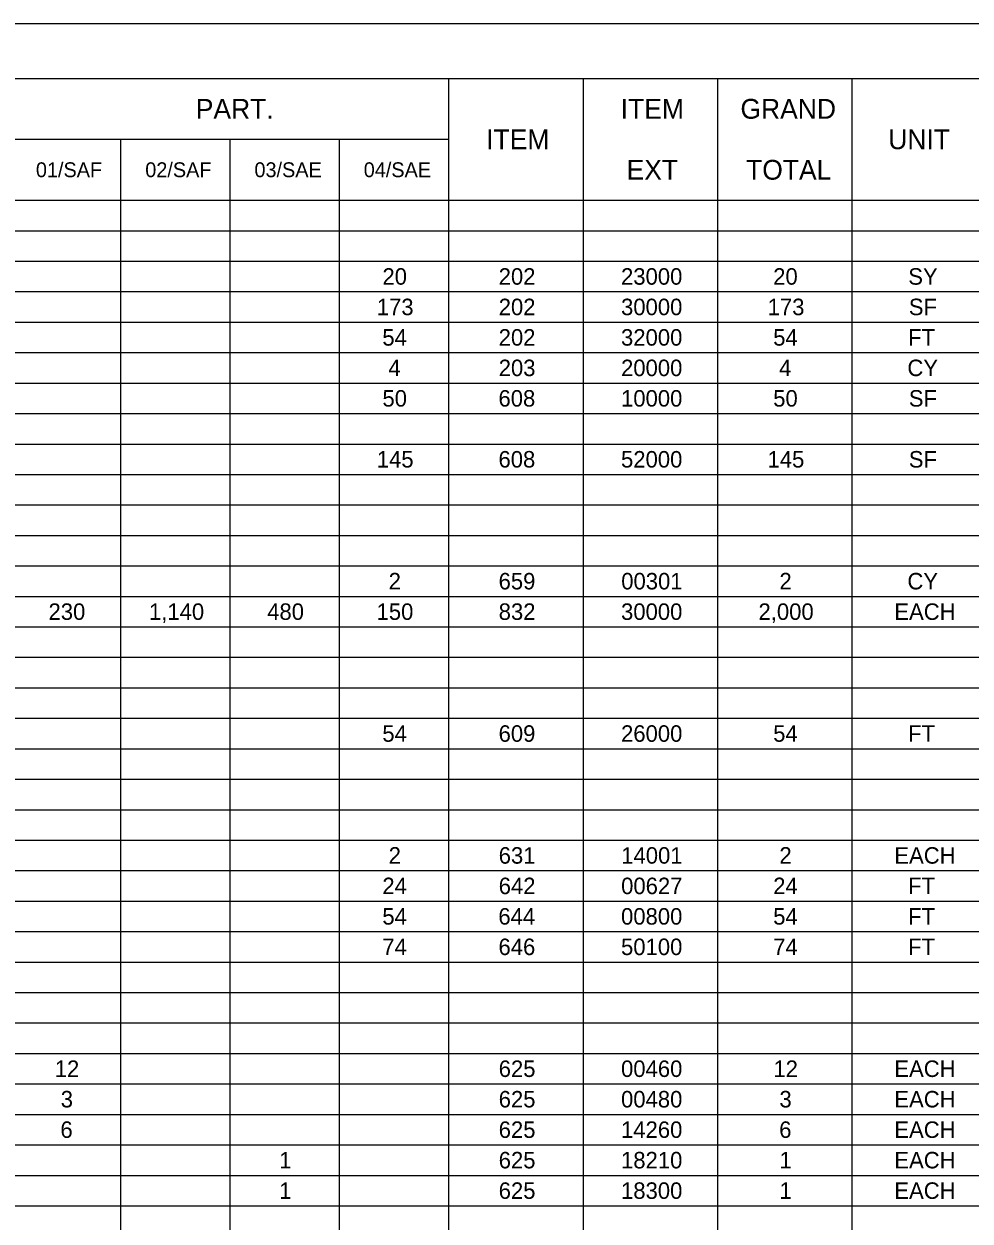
# Model space of a CAD drawing. Extents: x 0 to 34, y 0 to 22.
# Drawn here: x 8.65 to 17.34, y 11 to 22 of the extents above; entities that cross this region are included whole.
import ezdxf

# ---------------------------------------------------------------- set-up
doc = ezdxf.new("R2010")
doc.units = 0
for name, color, linetype in [('Default', 7, 'Continuous'), ('SH_Border', 7, 'Continuous'), ('SH_Cut_Line', 7, 'Continuous')]:
    doc.layers.add(name, color=color, linetype=linetype)

msp = doc.modelspace()

# ---------------------------------------------------------------- linework, layer by layer
at = {"layer": 'Default'}
for p, q in [((1.5, 21.5), (32, 21.5)), ((12.55, 21.5), (12.55, 0.5)), ((13.786, 21.5), (13.786, 0.5)), ((15.021, 21.5), (15.021, 0.5)), ((16.256, 21.5), (16.256, 0.5)), ((1.5, 20.94), (12.55, 20.94)), ((9.537, 20.94), (9.537, 0.5)), ((10.541, 20.94), (10.541, 0.5)), ((11.546, 20.94), (11.546, 0.5)), ((1.5, 20.38), (32, 20.38)), ((1.5, 20.1), (32, 20.1)), ((1.5, 19.82), (32, 19.82)), ((1.5, 19.54), (32, 19.54)), ((1.5, 19.26), (32, 19.26)), ((1.5, 18.98), (32, 18.98)), ((1.5, 18.7), (32, 18.7)), ((1.5, 18.42), (32, 18.42)), ((1.5, 18.14), (32, 18.14)), ((1.5, 17.86), (32, 17.86)), ((1.5, 17.58), (32, 17.58)), ((1.5, 17.3), (32, 17.3)), ((1.5, 17.02), (32, 17.02)), ((1.5, 16.74), (32, 16.74)), ((1.5, 16.46), (32, 16.46)), ((1.5, 16.18), (32, 16.18)), ((1.5, 15.9), (32, 15.9)), ((1.5, 15.62), (32, 15.62)), ((1.5, 15.34), (32, 15.34)), ((1.5, 15.06), (32, 15.06)), ((1.5, 14.78), (32, 14.78)), ((1.5, 14.5), (32, 14.5)), ((1.5, 14.22), (32, 14.22)), ((1.5, 13.94), (32, 13.94)), ((1.5, 13.66), (32, 13.66)), ((1.5, 13.38), (32, 13.38)), ((1.5, 13.1), (32, 13.1)), ((1.5, 12.82), (32, 12.82)), ((1.5, 12.54), (32, 12.54)), ((1.5, 12.26), (32, 12.26)), ((1.5, 11.98), (32, 11.98)), ((1.5, 11.7), (32, 11.7)), ((1.5, 11.42), (32, 11.42)), ((1.5, 11.14), (32, 11.14))]:
    msp.add_line(p, q, dxfattribs=at)
at = {"layer": 'SH_Border'}
msp.add_lwpolyline([(1.5, 21.5), (33.5, 21.5), (33.5, 0.5), (1.5, 0.5)], close=True, dxfattribs=at)
at = {"layer": 'SH_Cut_Line'}
msp.add_lwpolyline([(0, 0), (34, 0), (34, 22), (0, 22)], close=True, dxfattribs=at)

# ---------------------------------------------------------------- texts
at = {"layer": 'Default'}
for s, height, p in [('PART.', 0.1818, (10.228, 21.129)), ('ITEM', 0.1818, (14.132, 21.129)), ('GRAND', 0.1818, (15.232, 21.129)), ('ITEM', 0.1818, (12.896, 20.849)), ('UNIT', 0.1818, (16.59, 20.849)), ('01/SAF', 0.1364, (8.759, 20.592)), ('02/SAF', 0.1364, (9.764, 20.592)), ('03/SAE', 0.1364, (10.767, 20.592)), ('04/SAE', 0.1364, (11.771, 20.592)), ('EXT', 0.1818, (14.186, 20.569)), ('TOTAL', 0.1818, (15.284, 20.569)), ('20', 0.1515, (11.943, 19.604)), ('202', 0.1515, (13.011, 19.604)), ('23000', 0.1515, (14.135, 19.604)), ('20', 0.1515, (15.533, 19.604)), ('SY', 0.1515, (16.774, 19.604)), ('173', 0.1515, (11.891, 19.324)), ('202', 0.1515, (13.011, 19.324)), ('30000', 0.1515, (14.135, 19.324)), ('173', 0.1515, (15.482, 19.324)), ('SF', 0.1515, (16.779, 19.324)), ('54', 0.1515, (11.942, 19.044)), ('202', 0.1515, (13.011, 19.044)), ('32000', 0.1515, (14.135, 19.044)), ('54', 0.1515, (15.533, 19.044)), ('FT', 0.1515, (16.773, 19.044)), ('4', 0.152, (11.997, 18.764)), ('203', 0.1515, (13.011, 18.764)), ('20000', 0.1515, (14.135, 18.764)), ('4', 0.152, (15.587, 18.764)), ('CY', 0.1515, (16.766, 18.764)), ('50', 0.1515, (11.943, 18.484)), ('608', 0.1515, (13.009, 18.484)), ('10000', 0.1515, (14.135, 18.484)), ('50', 0.1515, (15.533, 18.484)), ('SF', 0.1515, (16.779, 18.484)), ('145', 0.1515, (11.891, 17.924)), ('608', 0.1515, (13.009, 17.924)), ('52000', 0.1515, (14.135, 17.924)), ('145', 0.1515, (15.481, 17.924)), ('SF', 0.1515, (16.779, 17.924)), ('2', 0.152, (12, 16.804)), ('659', 0.1515, (13.01, 16.804)), ('00301', 0.1515, (14.137, 16.804)), ('2', 0.152, (15.59, 16.804)), ('CY', 0.1515, (16.766, 16.804)), ('230', 0.1515, (8.875, 16.524)), ('1,140', 0.1515, (9.798, 16.524)), ('480', 0.1515, (10.884, 16.524)), ('150', 0.1515, (11.889, 16.524)), ('832', 0.1515, (13.011, 16.524)), ('30000', 0.1515, (14.135, 16.524)), ('2,000', 0.1515, (15.398, 16.524)), ('EACH', 0.1515, (16.646, 16.524)), ('54', 0.1515, (11.942, 15.404)), ('609', 0.1515, (13.01, 15.404)), ('26000', 0.1515, (14.135, 15.404)), ('54', 0.1515, (15.533, 15.404)), ('FT', 0.1515, (16.773, 15.404)), ('2', 0.152, (12, 14.284)), ('631', 0.1515, (13.011, 14.284)), ('14001', 0.1515, (14.137, 14.284)), ('2', 0.152, (15.59, 14.284)), ('EACH', 0.1515, (16.646, 14.284)), ('24', 0.1515, (11.942, 14.004)), ('642', 0.1515, (13.011, 14.004)), ('00627', 0.1515, (14.136, 14.004)), ('24', 0.1515, (15.533, 14.004)), ('FT', 0.1515, (16.773, 14.004)), ('54', 0.1515, (11.942, 13.724)), ('644', 0.1515, (13.008, 13.724)), ('00800', 0.1515, (14.135, 13.724)), ('54', 0.1515, (15.533, 13.724)), ('FT', 0.1515, (16.773, 13.724)), ('74', 0.1515, (11.942, 13.444)), ('646', 0.1515, (13.009, 13.444)), ('50100', 0.1515, (14.135, 13.444)), ('74', 0.1515, (15.533, 13.444)), ('FT', 0.1515, (16.773, 13.444)), ('12', 0.1515, (8.932, 12.324)), ('625', 0.1515, (13.011, 12.324)), ('00460', 0.1515, (14.135, 12.324)), ('12', 0.1515, (15.535, 12.324)), ('EACH', 0.1515, (16.646, 12.324)), ('3', 0.152, (8.987, 12.044)), ('625', 0.1515, (13.011, 12.044)), ('00480', 0.1515, (14.135, 12.044)), ('3', 0.152, (15.59, 12.044)), ('EACH', 0.1515, (16.646, 12.044)), ('6', 0.152, (8.984, 11.764)), ('625', 0.1515, (13.011, 11.764)), ('14260', 0.1515, (14.135, 11.764)), ('6', 0.152, (15.588, 11.764)), ('EACH', 0.1515, (16.646, 11.764)), ('1', 0.152, (10.995, 11.484)), ('625', 0.1515, (13.011, 11.484)), ('18210', 0.1515, (14.135, 11.484)), ('1', 0.152, (15.59, 11.484)), ('EACH', 0.1515, (16.646, 11.484)), ('1', 0.152, (10.995, 11.204)), ('625', 0.1515, (13.011, 11.204)), ('18300', 0.1515, (14.135, 11.204)), ('1', 0.152, (15.59, 11.204)), ('EACH', 0.1515, (16.646, 11.204))]:
    msp.add_text(s, height=height, dxfattribs=at).set_placement(p)

doc.saveas('drawing.dxf')
